(* Logix 5000 project; controller MVI69ADM vendor 1 type 14 code 65 rev 12.1; software revision 12.03 *)
// Sample Ladder for MVI69-ADM

TASK MainTask (continuous, watchdog 500 ms) : MainProgram

MODULES
   Controller : vendor 1 type 14 code 65 (rev 12.1)
      LocalENB : 1769-L35E Ethernet Port (rev 12.1)
      Local : CompactBus (rev 12.1, Output RPI 2 ms)
         MVI69 : 1769-MODULE (rev 1.1, Output RPI 2 ms)
END_MODULES

TYPE ADM_BLK_STATS :
STRUCT
   ReadCnt : INT;
   WriteCnt : INT;
   ParseCnt : INT;
   EventCnt : INT;
   CmdCnt : INT;
   ErrCnt : INT;
END_STRUCT
END_TYPE

TYPE ADM_PORT_ERROR :
STRUCT
   CmdList : INT;
   CmdListResp : INT;
   CmdListErrs : INT;
   Requests : INT;
   Responses : INT;
   ErrSent : INT;
   ErrRec : INT;
END_STRUCT
END_TYPE

TYPE ADM_STATUS :
STRUCT
   Pass_Cnt : INT;
   Prod : SINT[5];
   Rev : SINT[5];
   Op : SINT[5];
   Run : SINT[5];
   PortErr : ADM_PORT_ERROR[2];
   BlkStats : ADM_BLK_STATS;
   Port1_CurErr : INT;
   Port1_LastErr : INT;
   Port2_CurErr : INT;
   Port2_LastErr : INT;
END_STRUCT
END_TYPE

TYPE ADMBackplane :
STRUCT
   LastRead : INT;
   LastWrite : INT;
   BlockIndex : INT;
   BootTimer : TIMER;
END_STRUCT
END_TYPE

TYPE ADMBlockRequest :
STRUCT
   Warmboot : BOOL;
   Coldboot : BOOL;
END_STRUCT
END_TYPE

TYPE ADMModuleDef :
STRUCT
   BlockTransferSize : INT;
   ReadData : INT[720];
   WriteData : INT[720];
   BP : ADMBackplane;
   ModuleStatus : ADM_STATUS;
   BlockRequest : ADMBlockRequest;
END_STRUCT
END_TYPE

VAR_GLOBAL   (* controller tags *)
   ADM : ADMModuleDef;
END_VAR

PROGRAM MainProgram   (* routine attr 65 MainRoutine *)
VAR
   MCM : DINT;
END_VAR

ROUTINE MainRoutine   (* ladder *)
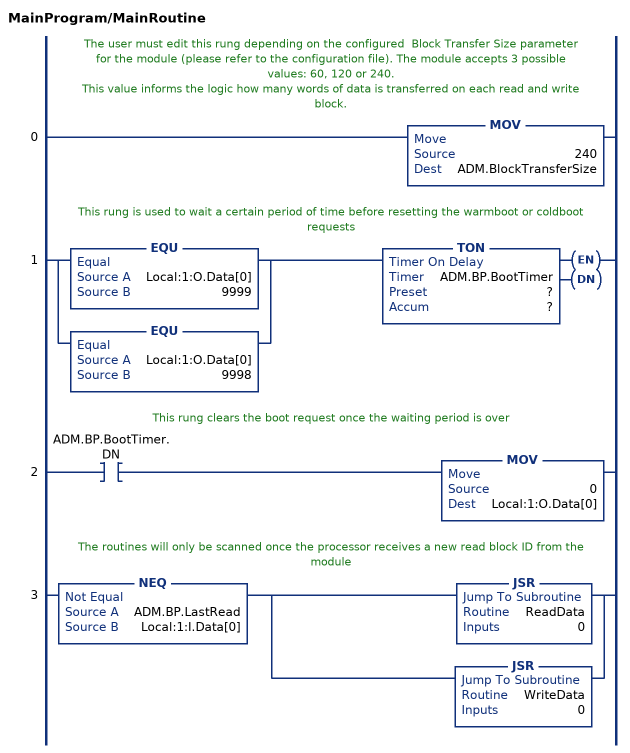
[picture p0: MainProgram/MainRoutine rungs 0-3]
   // The user must edit this rung depending on the configured  Block Transfer Size parameter for the module (please refer to the configuration file). The module accepts 3 possible values: 60, 120 or 240.
   // This value informs the logic how many words of data is transferred on each read and write block.
   0: MOV(240,ADM.BlockTransferSize);
   // This rung is used to wait a certain period of time before resetting the warmboot or coldboot requests
   1: [EQU(Local:1:O.Data[0],9999) ,EQU(Local:1:O.Data[0],9998) ]TON(ADM.BP.BootTimer,?,?);
   // This rung clears the boot request once the waiting period is over
   2: XIC(ADM.BP.BootTimer.DN)MOV(0,Local:1:O.Data[0]);
   // The routines will only be scanned once the processor receives a new read block ID from the module
   3: NEQ(ADM.BP.LastRead,Local:1:I.Data[0])[JSR(ReadData,0) ,JSR(WriteData,0) ];
END_ROUTINE

ROUTINE ReadData   (* ladder *)
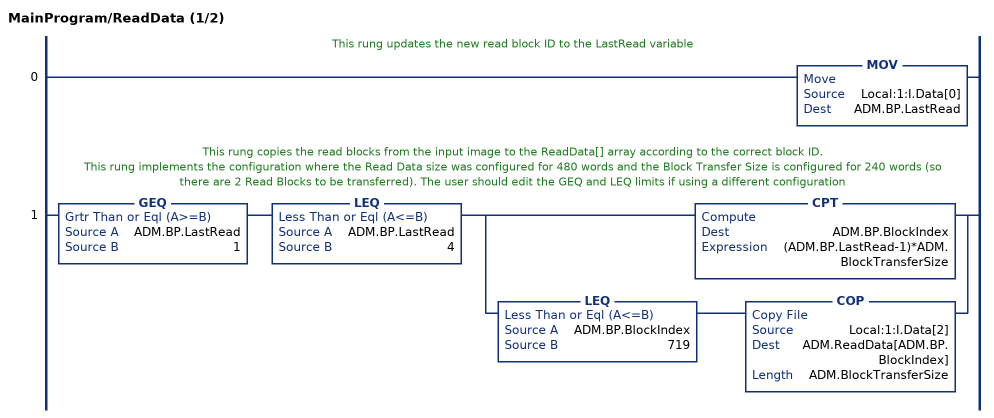
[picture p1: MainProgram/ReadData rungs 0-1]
   // This rung updates the new read block ID to the LastRead variable
   0: MOV(Local:1:I.Data[0],ADM.BP.LastRead);
   // This rung copies the read blocks from the input image to the ReadData[] array according to the correct block ID.
   // This rung implements the configuration where the Read Data size was configured for 480 words and the Block Transfer Size is configured for 240 words (so there are 2 Read Blocks to be transferred). The user should edit the GEQ and LEQ limits if using a different configuration
   1: GEQ(ADM.BP.LastRead,1)LEQ(ADM.BP.LastRead,4)[CPT(ADM.BP.BlockIndex,(ADM.BP.LastRead-1)*ADM.BlockTransferSize) ,LEQ(ADM.BP.BlockIndex,719) COP(Local:1:I.Data[2],ADM.ReadData[ADM.BP.BlockIndex],ADM.BlockTransferSize) ];
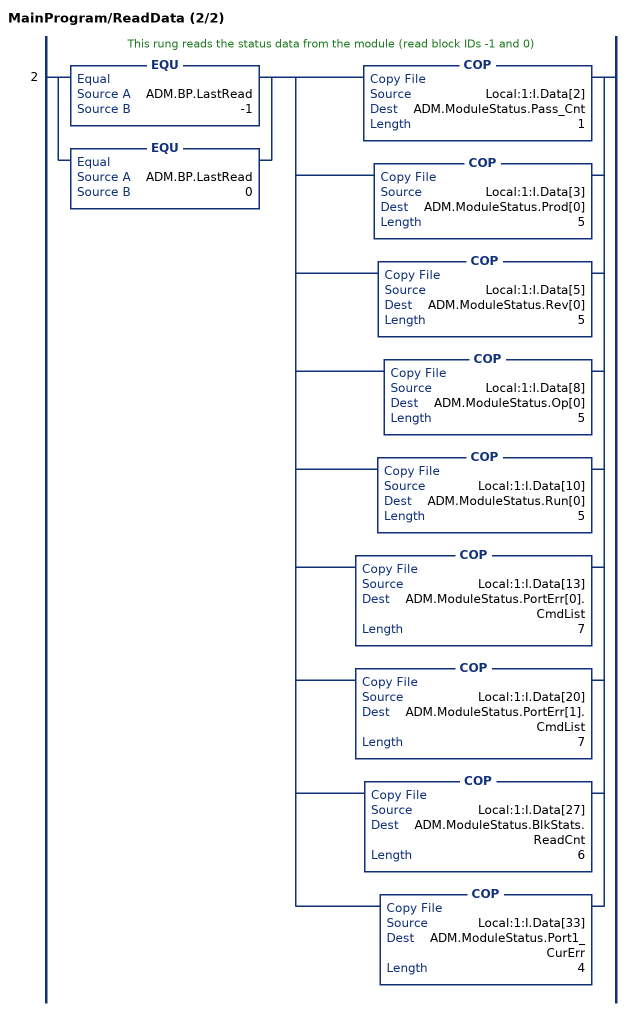
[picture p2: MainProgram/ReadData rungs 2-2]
   // This rung reads the status data from the module (read block IDs -1 and 0)
   2: [EQU(ADM.BP.LastRead,-1) ,EQU(ADM.BP.LastRead,0) ][COP(Local:1:I.Data[2],ADM.ModuleStatus.Pass_Cnt,1) ,COP(Local:1:I.Data[3],ADM.ModuleStatus.Prod[0],5) ,COP(Local:1:I.Data[5],ADM.ModuleStatus.Rev[0],5) ,COP(Local:1:I.Data[8],ADM.ModuleStatus.Op[0],5) ,COP(Local:1:I.Data[10],ADM.ModuleStatus.Run[0],5) ,COP(Local:1:I.Data[13],ADM.ModuleStatus.PortErr[0].CmdList,7) ,COP(Local:1:I.Data[20],ADM.ModuleStatus.PortErr[1].CmdList,7) ,COP(Local:1:I.Data[27],ADM.ModuleStatus.BlkStats.ReadCnt,6) ,COP(Local:1:I.Data[33],ADM.ModuleStatus.Port1_CurErr,4) ];
END_ROUTINE

ROUTINE WriteData   (* ladder *)
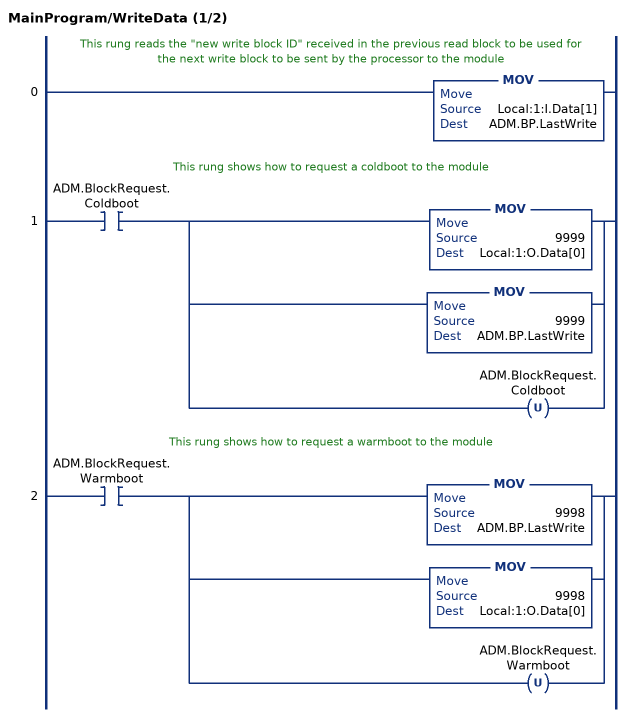
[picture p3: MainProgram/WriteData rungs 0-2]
   // This rung reads the "new write block ID" received in the previous read block to be used for the next write block to be sent by the processor to the module
   0: MOV(Local:1:I.Data[1],ADM.BP.LastWrite);
   // This rung shows how to request a coldboot to the module
   1: XIC(ADM.BlockRequest.Coldboot)[MOV(9999,Local:1:O.Data[0]) ,MOV(9999,ADM.BP.LastWrite) ,OTU(ADM.BlockRequest.Coldboot) ];
   // This rung shows how to request a warmboot to the module
   2: XIC(ADM.BlockRequest.Warmboot)[MOV(9998,ADM.BP.LastWrite) ,MOV(9998,Local:1:O.Data[0]) ,OTU(ADM.BlockRequest.Warmboot) ];
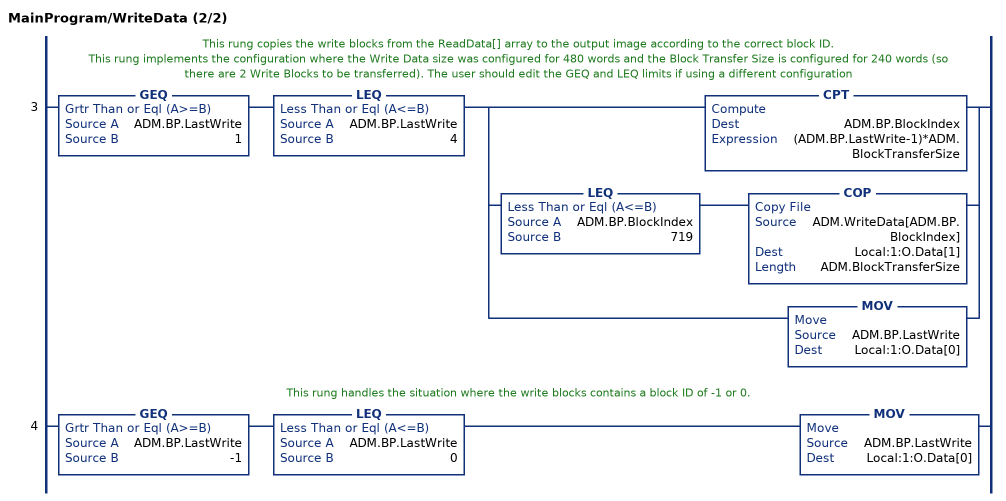
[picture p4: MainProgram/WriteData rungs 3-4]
   // This rung copies the write blocks from the ReadData[] array to the output image according to the correct block ID.
   // This rung implements the configuration where the Write Data size was configured for 480 words and the Block Transfer Size is configured for 240 words (so there are 2 Write Blocks to be transferred). The user should edit the GEQ and LEQ limits if using a different configuration
   3: GEQ(ADM.BP.LastWrite,1)LEQ(ADM.BP.LastWrite,4)[CPT(ADM.BP.BlockIndex,(ADM.BP.LastWrite-1)*ADM.BlockTransferSize) ,LEQ(ADM.BP.BlockIndex,719) COP(ADM.WriteData[ADM.BP.BlockIndex],Local:1:O.Data[1],ADM.BlockTransferSize) ,MOV(ADM.BP.LastWrite,Local:1:O.Data[0]) ];
   // This rung handles the situation where the write blocks contains a block ID of -1 or 0.
   4: GEQ(ADM.BP.LastWrite,-1)LEQ(ADM.BP.LastWrite,0)MOV(ADM.BP.LastWrite,Local:1:O.Data[0]);
END_ROUTINE
END_PROGRAM
